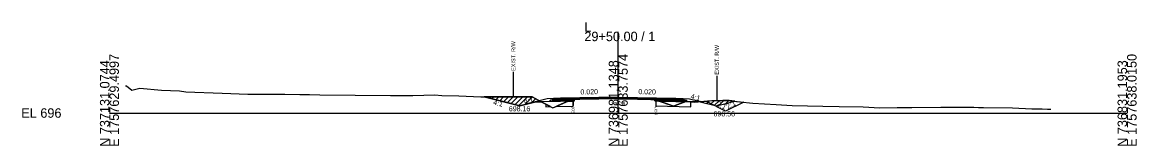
# Model space of a CAD drawing. Extents: x -26 to 4303, y -10 to 9577.
# Drawn here: x 974.3 to 1302.8, y 9490.3 to 9526.9 of the extents above; entities that cross this region are included whole.
import ezdxf

# ---------------------------------------------------------------- set-up
doc = ezdxf.new("R2010")
doc.units = 0
for name, color, linetype in [('Exist CMT Pavement', 7, 'Continuous'), ('Old_Level_10', 7, 'Continuous'), ('Old_Level_2', 7, 'Continuous'), ('Pattern 1', 7, 'Continuous'), ('Prop CMT Conc Surface', 7, 'Continuous'), ('Prop CMT Concrete Structures', 7, 'Continuous'), ('Prop CMT Concrete Wall', 7, 'Continuous'), ('Prop CMT Pvmt Course 1', 7, 'Continuous'), ('Prop CMT Pvmt Course 1 CG', 7, 'Continuous'), ('Prop CMT Pvmt Course 1 Wedge', 7, 'Continuous'), ('Prop CMT Pvmt Course 2', 7, 'Continuous'), ('Prop CMT Pvmt Course 2 Wedge', 7, 'Continuous'), ('Prop CMT Pvmt Course 3', 7, 'Continuous'), ('Prop CMT Pvmt Surface', 7, 'Continuous'), ('Prop CMT Pvmt Surface Shoulder', 7, 'Continuous'), ('Prop CMT Pvmt Wedge Surface 1', 7, 'Continuous'), ('Prop CMT Pvmt Wedge Surface 2', 7, 'Continuous'), ('Prop CMT Pvmt Wedge Surface 3', 7, 'Continuous'), ('Prop CMT Shld Paved Course 1', 7, 'Continuous'), ('Prop CMT Shld Paved Course 2', 7, 'Continuous'), ('Prop CMT Shld Paved Course 3', 7, 'Continuous'), ('Prop CMT Slope Grass', 7, 'Continuous'), ('Prop CMT Subgrade Earthwork', 7, 'Continuous'), ('Prop Road Sect_ Recs - UC Shallow (Outline)', 7, 'Continuous'), ('Prop Shade Light', 7, 'Continuous'), ('Prop XS DDE Elevations', 7, 'Continuous'), ('Prop XS Ditch Standard Text', 7, 'Continuous'), ('Prop XS Earthwork Shape', 7, 'Continuous'), ('Prop XS Hydro Elevations', 7, 'Continuous'), ('Prop XS SE Text', 7, 'Continuous'), ('Prop XS Side Slope Text', 7, 'Continuous'), ('Prop XS Wedging', 7, 'Continuous')]:
    doc.layers.add(name, color=color, linetype=linetype)

msp = doc.modelspace()

# ---------------------------------------------------------------- linework, layer by layer
at = {"layer": 'Exist CMT Pavement'}
for points in [[(1150, 9504.7), (1133, 9504.36)], [(1150, 9504.7), (1167, 9504.36)]]:
    msp.add_lwpolyline(points, dxfattribs=at)
at = {"layer": 'Old_Level_10'}
for p, q in [((1176.22, 9503.26), (1174.22, 9503.36)), ((1181.62, 9500.56), (1176.22, 9503.26)), ((1186.97, 9503.23), (1181.62, 9500.56))]:
    msp.add_line(p, q, dxfattribs=at)
at = {"layer": 'Old_Level_2'}
for p, q in [((1150, 9500), (1150, 9524.05)), ((1150, 9500), (1150, 9524.05)), ((1000, 9500), (1150, 9500)), ((1000, 9500), (1150, 9500)), ((1150, 9500), (1300, 9500)), ((1150, 9500), (1300, 9500))]:
    msp.add_line(p, q, dxfattribs=at)
at = {"layer": 'Pattern 1'}
for p, q in [((1110.53, 9504.75), (1110.54, 9504.76)), ((1111.66, 9504.47), (1111.95, 9504.76)), ((1112.79, 9504.19), (1113.36, 9504.76)), ((1113.93, 9503.91), (1114.77, 9504.76)), ((1115.06, 9503.62), (1116.19, 9504.75)), ((1116.19, 9503.34), (1117.6, 9504.75)), ((1117.32, 9503.06), (1119.01, 9504.75)), ((1118.45, 9502.77), (1120.42, 9504.74)), ((1119.58, 9502.49), (1121.83, 9504.74)), ((1120.71, 9502.21), (1123.25, 9504.74)), ((1122.41, 9502.49), (1124.64, 9504.72)), ((1124.29, 9502.96), (1125.56, 9504.23)), ((1126.07, 9503.32), (1126.49, 9503.74)), ((1136.17, 9503.54), (1136.69, 9504.06)), ((1161.11, 9503.58), (1161.32, 9503.79)), ((1174.95, 9503.15), (1175.24, 9503.44)), ((1176.08, 9502.87), (1176.77, 9503.55)), ((1177.21, 9502.58), (1178.24, 9503.61)), ((1178.35, 9502.3), (1179.7, 9503.65)), ((1179.79, 9502.34), (1181.16, 9503.7)), ((1181.68, 9502.81), (1182.55, 9503.67)), ((1183.57, 9503.28), (1183.83, 9503.55))]:
    msp.add_line(p, q, dxfattribs=at)
for points in [[(1121, 9502.14), (1125.72, 9503.32), (1127.25, 9503.35), (1124.59, 9504.74), (1121.09, 9504.74), (1113.29, 9504.76), (1110.49, 9504.76)], [(1136.71, 9503.53), (1136.71, 9504.2), (1135.18, 9503.51)], [(1179, 9502.14), (1184.41, 9503.49), (1182.71, 9503.66), (1182.03, 9503.73), (1180.83, 9503.69), (1177.63, 9503.59), (1176.32, 9503.53), (1174.15, 9503.35)]]:
    msp.add_lwpolyline(points, close=True, dxfattribs=at)
msp.add_lwpolyline([(1161.09, 9503.87), (1161.09, 9503.58), (1161.93, 9503.56), (1161.09, 9503.87)], dxfattribs=at)
at = {"layer": 'Prop CMT Conc Surface'}
for points in [[(1136.71, 9504.19), (1133, 9504.11)], [(1133, 9504.11), (1133, 9503.9)], [(1133, 9503.9), (1136.71, 9503.98)], [(1136.71, 9503.98), (1136.71, 9504.19)], [(1161.09, 9504.02), (1161.09, 9504.23)], [(1161.09, 9504.23), (1167, 9504.11)], [(1167, 9503.9), (1161.09, 9504.02)], [(1167, 9504.11), (1167, 9503.9)]]:
    msp.add_lwpolyline(points, dxfattribs=at)
at = {"layer": 'Prop CMT Concrete Structures'}
for points in [[(1150, 9504.58), (1136.71, 9504.31)], [(1150, 9504.58), (1161.09, 9504.36)], [(1133, 9504.11), (1133, 9504.36)], [(1136.71, 9504.19), (1133, 9504.11)], [(1136.71, 9504.31), (1136.71, 9504.19)], [(1161.09, 9504.36), (1161.09, 9504.23)], [(1161.09, 9504.23), (1167, 9504.11)], [(1167, 9504.11), (1167, 9504.36)]]:
    msp.add_lwpolyline(points, dxfattribs=at)
at = {"layer": 'Prop CMT Pvmt Course 1'}
for points in [[(1136.71, 9503.98), (1133, 9503.9)], [(1133, 9503.9), (1133, 9503.57)], [(1133, 9503.57), (1136.71, 9503.64)], [(1136.71, 9503.64), (1136.71, 9503.98)], [(1161.09, 9504.02), (1167, 9503.9)], [(1161.09, 9503.69), (1161.09, 9504.02)], [(1167, 9503.57), (1161.09, 9503.69)], [(1167, 9503.9), (1167, 9503.57)]]:
    msp.add_lwpolyline(points, dxfattribs=at)
at = {"layer": 'Prop CMT Pvmt Course 1 Wedge'}
for points in [[(1161.09, 9503.9), (1160.96, 9503.97)], [(1160.96, 9503.97), (1161.09, 9503.97)], [(1161.09, 9503.97), (1161.09, 9503.9)]]:
    msp.add_lwpolyline(points, dxfattribs=at)
at = {"layer": 'Prop CMT Pvmt Course 2'}
for points in [[(1133, 9504.36), (1131, 9504.32), (1130.74, 9504.07)], [(1130.74, 9504.07), (1133, 9504.11)], [(1133, 9504.11), (1133, 9504.36)], [(1167, 9504.36), (1169, 9504.32), (1169.26, 9504.07)], [(1167, 9504.11), (1167, 9504.36)], [(1169.26, 9504.07), (1167, 9504.11)]]:
    msp.add_lwpolyline(points, dxfattribs=at)
at = {"layer": 'Prop CMT Pvmt Course 2 Wedge'}
for points in [[(1131, 9504.32), (1129, 9504.16), (1121, 9502.16), (1110.59, 9504.76)], [(1169, 9504.32), (1171, 9504.16), (1174.22, 9503.36)], [(1184.49, 9503.48), (1184.49, 9503.48)]]:
    msp.add_lwpolyline(points, dxfattribs=at)
at = {"layer": 'Prop CMT Pvmt Course 3'}
for points in [[(1133, 9504.11), (1130.74, 9504.07), (1130.53, 9503.85)], [(1130.53, 9503.85), (1133, 9503.9)], [(1133, 9503.9), (1133, 9504.11)], [(1167, 9504.11), (1169.26, 9504.07), (1169.47, 9503.85)], [(1167, 9503.9), (1167, 9504.11)], [(1169.47, 9503.85), (1167, 9503.9)]]:
    msp.add_lwpolyline(points, dxfattribs=at)
at = {"layer": 'Prop CMT Pvmt Surface'}
for points in [[(1150, 9504.45), (1133, 9504.11)], [(1150, 9504.45), (1167, 9504.11)], [(1133, 9504.11), (1133, 9504.36)], [(1167, 9504.11), (1167, 9504.36)]]:
    msp.add_lwpolyline(points, dxfattribs=at)
at = {"layer": 'Prop CMT Pvmt Surface Shoulder'}
for points in [[(1136.98, 9504.32), (1137.1, 9504.31), (1137.13, 9504.31), (1137.75, 9504.29), (1139.2, 9504.3), (1139.45, 9504.31), (1139.83, 9504.31), (1139.88, 9504.31), (1140.15, 9504.31), (1142.38, 9504.32), (1142.58, 9504.32), (1144.88, 9504.31), (1145.02, 9504.31), (1147.38, 9504.29), (1147.4, 9504.29), (1147.82, 9504.3), (1149.04, 9504.3), (1149.88, 9504.29), (1149.88, 9504.29), (1149.89, 9504.29), (1150, 9504.29)], [(1150, 9504.29), (1152.39, 9504.22), (1154.74, 9504.19), (1154.89, 9504.19), (1157.18, 9504.1), (1157.39, 9504.09), (1159.61, 9504.03), (1159.89, 9504.02), (1160.29, 9504), (1160.49, 9503.99), (1160.69, 9504), (1160.75, 9504)]]:
    msp.add_lwpolyline(points, dxfattribs=at)
at = {"layer": 'Prop CMT Pvmt Wedge Surface 1'}
for p, q in [((1133.02, 9503.45), (1125.53, 9503.3)), ((1136.98, 9503.52), (1133.02, 9503.45)), ((1160.76, 9503.57), (1166.98, 9503.45)), ((1166.98, 9503.45), (1168.98, 9503.41)), ((1168.98, 9503.41), (1174.22, 9503.36))]:
    msp.add_line(p, q, dxfattribs=at)
for points in [[(1136.98, 9503.52), (1136.98, 9504.32)], [(1160.76, 9503.57), (1160.75, 9504)]]:
    msp.add_lwpolyline(points, dxfattribs=at)
at = {"layer": 'Prop CMT Pvmt Wedge Surface 2'}
for points in [[(1150, 9504.45), (1149.89, 9504.45), (1149.88, 9504.45), (1149.88, 9504.45), (1149.04, 9504.43), (1147.82, 9504.41), (1147.4, 9504.4), (1147.38, 9504.4), (1145.61, 9504.36), (1145.02, 9504.37), (1144.88, 9504.37), (1142.58, 9504.37), (1142.38, 9504.37), (1140.15, 9504.37), (1139.88, 9504.37), (1139.83, 9504.36), (1139.45, 9504.36), (1139.2, 9504.36), (1138.88, 9504.35)], [(1139.2, 9504.36), (1139.45, 9504.37), (1139.83, 9504.37), (1139.88, 9504.37), (1140.15, 9504.38), (1142.38, 9504.42), (1142.58, 9504.43), (1144.88, 9504.47), (1145.02, 9504.48), (1147.38, 9504.52), (1147.4, 9504.53), (1147.82, 9504.53), (1149.04, 9504.56), (1149.88, 9504.57), (1149.88, 9504.57), (1149.89, 9504.57), (1150, 9504.58)], [(1150, 9504.58), (1150, 9504.45)], [(1150, 9504.58), (1152.39, 9504.53), (1154.74, 9504.48), (1154.89, 9504.48), (1157.18, 9504.43), (1157.39, 9504.43), (1159.61, 9504.38), (1159.89, 9504.38), (1160.29, 9504.37), (1160.49, 9504.37), (1160.69, 9504.36), (1160.75, 9504.36), (1160.82, 9504.36), (1160.89, 9504.36), (1161.09, 9504.36)], [(1161.09, 9504.23), (1160.89, 9504.23), (1160.82, 9504.24), (1160.75, 9504.24), (1160.69, 9504.24), (1160.49, 9504.24), (1160.29, 9504.25), (1159.89, 9504.25), (1159.61, 9504.26), (1157.39, 9504.3), (1157.18, 9504.31), (1154.89, 9504.35), (1154.74, 9504.36), (1152.39, 9504.4), (1150, 9504.45)], [(1138.88, 9504.35), (1139.2, 9504.36)], [(1161.09, 9504.36), (1161.09, 9504.23)]]:
    msp.add_lwpolyline(points, dxfattribs=at)
at = {"layer": 'Prop CMT Pvmt Wedge Surface 3'}
for points in [[(1147.38, 9504.4), (1147.4, 9504.4), (1147.82, 9504.41), (1149.04, 9504.43), (1149.88, 9504.45), (1149.88, 9504.45), (1149.89, 9504.45), (1150, 9504.45)], [(1150, 9504.45), (1150, 9504.34)], [(1150, 9504.45), (1152.39, 9504.4), (1154.74, 9504.36), (1154.89, 9504.35), (1157.18, 9504.31), (1157.39, 9504.3), (1159.61, 9504.26), (1159.89, 9504.25), (1160.29, 9504.25), (1160.49, 9504.24), (1160.69, 9504.24), (1160.75, 9504.24), (1160.82, 9504.24), (1160.89, 9504.23), (1161.09, 9504.23)], [(1145.61, 9504.36), (1147.38, 9504.4)], [(1150, 9504.34), (1149.89, 9504.35), (1149.88, 9504.35), (1149.88, 9504.35), (1149.04, 9504.35), (1147.82, 9504.36), (1147.4, 9504.35), (1147.38, 9504.35), (1145.61, 9504.36)], [(1160.75, 9504.05), (1160.69, 9504.05), (1160.49, 9504.04), (1160.29, 9504.06), (1159.89, 9504.08), (1159.61, 9504.08), (1157.39, 9504.15), (1157.18, 9504.16), (1154.89, 9504.24), (1154.74, 9504.24), (1152.39, 9504.27), (1150, 9504.34)], [(1161.09, 9504.23), (1161.09, 9504.02)]]:
    msp.add_lwpolyline(points, dxfattribs=at)
at = {"layer": 'Prop CMT Shld Paved Course 1'}
for points in [[(1133, 9503.9), (1133, 9504.36)], [(1150, 9504.24), (1133, 9503.9)], [(1150, 9504.24), (1167, 9503.9)], [(1167, 9503.9), (1167, 9504.36)]]:
    msp.add_lwpolyline(points, dxfattribs=at)
at = {"layer": 'Prop CMT Shld Paved Course 2'}
for points in [[(1133, 9504.36), (1131, 9504.32)], [(1167, 9504.36), (1169, 9504.32)]]:
    msp.add_lwpolyline(points, dxfattribs=at)
at = {"layer": 'Prop CMT Shld Paved Course 3'}
for points in [[(1150, 9504.7), (1133, 9504.36)], [(1136.71, 9504.31), (1150, 9504.58)], [(1150, 9504.7), (1167, 9504.36)], [(1161.09, 9504.36), (1150, 9504.58)], [(1133, 9504.36), (1133, 9504.11)], [(1133, 9504.11), (1136.71, 9504.19)], [(1136.71, 9504.19), (1136.71, 9504.31)], [(1161.09, 9504.23), (1161.09, 9504.36)], [(1167, 9504.11), (1161.09, 9504.23)], [(1167, 9504.36), (1167, 9504.11)]]:
    msp.add_lwpolyline(points, dxfattribs=at)
at = {"layer": 'Prop CMT Slope Grass'}
msp.add_lwpolyline([(1004.75, 9508.02), (1005.07, 9507.99), (1006.57, 9506.76), (1008.93, 9507.3), (1015.37, 9506.74), (1020.7, 9506.59), (1022.51, 9506.27), (1033.19, 9505.83), (1040.79, 9505.55), (1046.1, 9505.56), (1051.72, 9505.53), (1056.1, 9505.48), (1059.02, 9505.49), (1062.02, 9505.4), (1082.87, 9505.16), (1086.12, 9505.17), (1089.43, 9505.15), (1095.94, 9505.33), (1097.95, 9505.2), (1102.98, 9505.11), (1109.47, 9504.77), (1120.41, 9504.74), (1124.59, 9504.74), (1130.74, 9501.51), (1132.1, 9502.11), (1136.98, 9504.32), (1137.1, 9504.31), (1137.75, 9504.29), (1140.15, 9504.31), (1142.58, 9504.32), (1145.02, 9504.31), (1147.4, 9504.29), (1147.82, 9504.3), (1149.04, 9504.3), (1150, 9504.29), (1152.39, 9504.22), (1154.89, 9504.19), (1157.61, 9504.09), (1159.89, 9504.02), (1160.49, 9503.99), (1160.75, 9504), (1161.32, 9503.78), (1166.26, 9502.05), (1167.6, 9502.51), (1169.94, 9503.42), (1172.57, 9503.22), (1176.59, 9503.56), (1182.02, 9503.73), (1189.69, 9502.96), (1196.54, 9502.55), (1201.27, 9502.21), (1210.28, 9501.99), (1215.11, 9501.92), (1222.16, 9501.85), (1227.11, 9501.57), (1232.21, 9501.64), (1236.53, 9501.62), (1245.1, 9501.72), (1246.2, 9501.73), (1254.83, 9501.72), (1256.21, 9501.65), (1257.67, 9501.67), (1266.21, 9501.49), (1271.92, 9501.28), (1274.93, 9501.19), (1276.52, 9501.1), (1277.51, 9501.15)], dxfattribs=at)
at = {"layer": 'Prop CMT Subgrade Earthwork'}
for points in [[(1133, 9503.9), (1130.53, 9503.85), (1130.03, 9503.84), (1129.69, 9503.5)], [(1129.69, 9503.5), (1133, 9503.57)], [(1133, 9503.57), (1133, 9503.9)], [(1167, 9503.9), (1169.47, 9503.85), (1169.97, 9503.84), (1170.31, 9503.5)], [(1167, 9503.57), (1167, 9503.9)], [(1170.31, 9503.5), (1167, 9503.57)]]:
    msp.add_lwpolyline(points, dxfattribs=at)
at = {"layer": 'Prop Road Sect_ Recs - UC Shallow (Outline)'}
msp.add_lwpolyline([(1128.62, 9502.63), (1128.64, 9501.87), (1130, 9501.9), (1128.62, 9502.62)], dxfattribs=at)
for points in [[(1135.18, 9503.51), (1131.7, 9501.94), (1136.71, 9502.04), (1136.71, 9503.54)], [(1161.09, 9502.08), (1171.36, 9501.87), (1171.35, 9503.31), (1170.25, 9503.4), (1169.89, 9503.4), (1167.69, 9502.54), (1166.26, 9502.05), (1161.93, 9503.56), (1161.09, 9503.58)]]:
    msp.add_lwpolyline(points, close=True, dxfattribs=at)
at = {"layer": 'Prop Shade Light'}
for p, q in [((1128.62, 9502.63), (1128.64, 9501.87)), ((1130, 9501.9), (1128.62, 9502.63)), ((1128.64, 9501.87), (1130, 9501.9)), ((1132.1, 9502.11), (1131.7, 9501.94)), ((1131.7, 9501.94), (1136.71, 9502.04)), ((1135.18, 9503.51), (1132.1, 9502.11)), ((1136.71, 9503.54), (1135.18, 9503.51)), ((1136.71, 9502.04), (1136.71, 9503.54)), ((1136.71, 9503.54), (1136.71, 9503.54)), ((1161.09, 9503.58), (1161.09, 9502.08)), ((1161.09, 9502.08), (1171.36, 9501.87)), ((1166.26, 9502.05), (1161.93, 9503.56)), ((1167.6, 9502.51), (1166.26, 9502.05)), ((1169.94, 9503.42), (1167.6, 9502.51)), ((1171.35, 9503.31), (1169.94, 9503.42)), ((1171.36, 9501.87), (1171.35, 9503.31)), ((1171.35, 9503.31), (1171.35, 9503.31))]:
    msp.add_line(p, q, dxfattribs=at)
msp.add_lwpolyline([(1161.93, 9503.56), (1161.3, 9503.58), (1161.09, 9503.58)], dxfattribs=at)
at = {"layer": 'Prop XS DDE Elevations'}
for points in [[(1126.76, 9503.6), (1125.53, 9503.3), (1121, 9502.16), (1110.59, 9504.76), (1120.41, 9504.74), (1124.59, 9504.74)], [(1127.28, 9503.33), (1125.53, 9503.3), (1126.76, 9503.6)], [(1135.14, 9503.49), (1133.02, 9503.45), (1127.28, 9503.33), (1130.74, 9501.51), (1132.1, 9502.11)], [(1136.98, 9503.52), (1135.14, 9503.49), (1136.98, 9504.32)], [(1137.1, 9504.31), (1137.13, 9504.31), (1137.75, 9504.29)], [(1139.88, 9504.31), (1140.15, 9504.31), (1137.75, 9504.29), (1139.2, 9504.3), (1139.45, 9504.31), (1139.83, 9504.31)], [(1140.15, 9504.31), (1142.58, 9504.32), (1142.38, 9504.32)], [(1149.04, 9504.3), (1150, 9504.29), (1149.88, 9504.29)], [(1152.39, 9504.22), (1154.89, 9504.19), (1154.74, 9504.19)], [(1154.89, 9504.19), (1157.18, 9504.1), (1157.39, 9504.09), (1157.61, 9504.09)], [(1160.29, 9504), (1160.49, 9503.99), (1159.89, 9504.02)], [(1160.49, 9503.99), (1160.75, 9504), (1160.69, 9504)], [(1161.32, 9503.78), (1161.99, 9503.55), (1160.76, 9503.57), (1160.75, 9504)], [(1161.99, 9503.55), (1166.98, 9503.45), (1168.98, 9503.41), (1169.88, 9503.4), (1167.6, 9502.51), (1166.26, 9502.05)], [(1169.88, 9503.4), (1169.94, 9503.42), (1170.31, 9503.39)], [(1170.31, 9503.39), (1174.22, 9503.36), (1172.57, 9503.22)]]:
    msp.add_lwpolyline(points, close=True, dxfattribs=at)
at = {"layer": 'Prop XS Ditch Standard Text'}
for p, q in [((1119.06, 9512.15), (1119.06, 9504.75)), ((1179.06, 9511.03), (1179.06, 9503.63)), ((1136.71, 9504.27), (1136.71, 9502.22)), ((1161.09, 9503.9), (1161.09, 9501.85))]:
    msp.add_line(p, q, dxfattribs=at)
at = {"layer": 'Prop XS Earthwork Shape'}
msp.add_lwpolyline([(1186.97, 9503.23), (1181.62, 9500.56), (1176.22, 9503.26), (1174.22, 9503.36), (1176.59, 9503.56), (1182.02, 9503.73)], close=True, dxfattribs=at)
at = {"layer": 'Prop XS Wedging'}
for p, q in [((1150, 9504.58), (1137.03, 9504.32)), ((1160.75, 9504.36), (1150, 9504.58)), ((1157.55, 9504.3), (1157.34, 9504.1)), ((1157.34, 9504.1), (1157.55, 9504.3)), ((1157.55, 9504.3), (1157.34, 9504.1)), ((1157.34, 9504.1), (1157.61, 9504.09)), ((1161.08, 9504.23), (1157.55, 9504.3)), ((1157.55, 9504.3), (1160.75, 9504.24)), ((1160.75, 9504.24), (1157.55, 9504.3)), ((1160.75, 9504), (1160.75, 9504.4)), ((1160.75, 9504.24), (1160.75, 9504.36)), ((1160.75, 9504), (1160.75, 9504.24))]:
    msp.add_line(p, q, dxfattribs=at)
for points in [[(1137.03, 9504.32), (1137.1, 9504.31), (1137.75, 9504.29), (1140.15, 9504.31), (1142.58, 9504.32), (1145.02, 9504.31), (1147.4, 9504.29), (1147.82, 9504.3), (1149.04, 9504.3), (1150, 9504.29), (1152.39, 9504.22), (1154.89, 9504.19), (1157.34, 9504.1)], [(1157.61, 9504.09), (1159.89, 9504.02), (1160.49, 9503.99), (1160.75, 9504)]]:
    msp.add_lwpolyline(points, dxfattribs=at)

# ---------------------------------------------------------------- texts
at = {"layer": 'Old_Level_2'}
for s, p in [('29+50.00 / 1', (1140, 9521.25)), ('29+50.00 / 1', (1140, 9521.25)), ('L', (1140, 9524.05)), ('L', (1140, 9524.05)), ('EL 696', (974, 9498.6)), ('EL 696', (974, 9498.6))]:
    msp.add_text(s, height=2.8, dxfattribs=at).set_placement(p)
for s, p in [('N 737131.0744', (1000, 9490)), ('N 737131.0744', (1000, 9490)), ('E 1757629.4997', (1002.8, 9490)), ('E 1757629.4997', (1002.8, 9490)), ('N 736981.1348', (1150, 9490)), ('N 736981.1348', (1150, 9490)), ('E 1757633.7574', (1152.8, 9490)), ('E 1757633.7574', (1152.8, 9490)), ('N 736831.1953', (1300, 9490)), ('N 736831.1953', (1300, 9490)), ('E 1757638.0150', (1302.8, 9490)), ('E 1757638.0150', (1302.8, 9490))]:
    msp.add_text(s, height=2.8, rotation=90, dxfattribs=at).set_placement(p)
at = {"layer": 'Prop CMT Concrete Wall'}
for rotation, p in [(334.1383, (1178.84, 9502.22)), (25.8617, (1182.27, 9501.14))]:
    msp.add_text('2:1', height=1.5, rotation=rotation, dxfattribs=at).set_placement(p)
msp.add_text('696.56', height=1.5, dxfattribs=at).set_placement((1178.07, 9499))
at = {"layer": 'Prop CMT Pvmt Course 1 CG'}
msp.add_text('700.29', height=1, dxfattribs=at).set_placement((1147.87, 9502.29))
at = {"layer": 'Prop XS Ditch Standard Text'}
for s, height, p in [('EXIST. R/W', 1.181, (1119.65, 9512.45)), ('EXIST. R/W', 1.181, (1179.65, 9511.34)), ('EOP', 0.787, (1137.1, 9499.83)), ('EOP', 0.787, (1161.48, 9499.45))]:
    msp.add_text(s, height=height, rotation=90, dxfattribs=at).set_placement(p)
at = {"layer": 'Prop XS Hydro Elevations'}
msp.add_text('698.16', height=1.5, dxfattribs=at).set_placement((1117.74, 9500.51))
at = {"layer": 'Prop XS SE Text'}
for rotation, p in [(1.1458, (1138.86, 9505.48)), (358.8542, (1155.9, 9505.58))]:
    msp.add_text('0.020', height=1.5, rotation=rotation, dxfattribs=at).set_placement(p)
at = {"layer": 'Prop XS Side Slope Text'}
for rotation, p in [(14.0362, (1122.33, 9502.66)), (345.9638, (1171.21, 9504.29)), (345.9638, (1113.02, 9502.53))]:
    msp.add_text('4:1', height=1.5, rotation=rotation, dxfattribs=at).set_placement(p)

doc.saveas('drawing.dxf')
